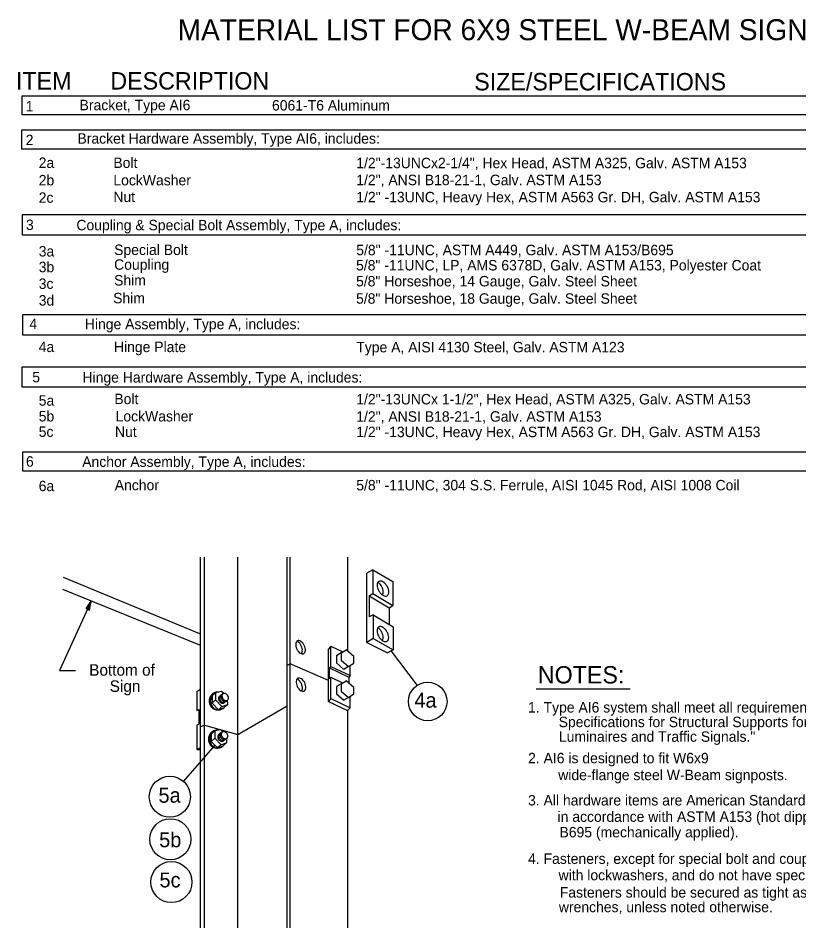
# Model space of a CAD drawing. Extents: x 12.3 to 19.6, y 5.8 to 16.1.
# Drawn here: x 12.33 to 16.82, y 10.9 to 16.09 of the extents above; entities that cross this region are included whole.
import ezdxf

# ---------------------------------------------------------------- set-up
doc = ezdxf.new("R2010")
doc.units = 0
for name, color, linetype in [('DETL-DIMS', 7, 'Continuous'), ('DETL-LINE', 7, 'Continuous'), ('DETL-NOTE', 7, 'Continuous')]:
    doc.layers.add(name, color=color, linetype=linetype)

msp = doc.modelspace()

# ---------------------------------------------------------------- linework, layer by layer
at = {"layer": 'DETL-DIMS'}
for p, q in [((12.7167, 12.6931), (12.7467, 12.7361)), ((12.7467, 12.7361), (12.7217, 12.6911)), ((12.7257, 12.6891), (12.7467, 12.7361)), ((12.7467, 12.7361), (12.7307, 12.6871)), ((12.7357, 12.6851), (12.7467, 12.7361)), ((12.7167, 12.6931), (12.7357, 12.6851))]:
    msp.add_line(p, q, dxfattribs=at)
msp.add_lwpolyline([(12.7467, 12.7361), (12.5633, 12.3374), (12.6551, 12.3374)], dxfattribs=at)
at = {"layer": 'DETL-LINE'}
for p, q in [((13.3751, 8.942), (13.3751, 12.9888)), ((13.3981, 8.9369), (13.3981, 12.9888)), ((13.5899, 8.9603), (13.5899, 12.9888)), ((13.8741, 8.7423), (13.8741, 12.9888)), ((13.8901, 8.7359), (13.8901, 12.9888)), ((14.2196, 12.9888), (14.2196, 12.4502)), ((14.3668, 12.9167), (14.3308, 12.8962)), ((14.3308, 12.4991), (14.3308, 12.8962)), ((14.3668, 12.9167), (14.4816, 12.8481)), ((14.3668, 12.9167), (14.3668, 12.7802)), ((13.3716, 12.5481), (12.5869, 12.8713)), ((14.4816, 12.8481), (14.4816, 12.7115)), ((13.3709, 12.4829), (12.5823, 12.8027)), ((14.3451, 12.7669), (14.3668, 12.7802)), ((14.3668, 12.7802), (14.4816, 12.7115)), ((14.3451, 12.7669), (14.4599, 12.6983)), ((14.3451, 12.7669), (14.3451, 12.6452)), ((14.4599, 12.6983), (14.4816, 12.7115)), ((14.4599, 12.6983), (14.4599, 12.6022)), ((14.3685, 12.6569), (14.3451, 12.6452)), ((14.3685, 12.6569), (14.4833, 12.5882)), ((14.3685, 12.6569), (14.3685, 12.5206)), ((14.4833, 12.5882), (14.4833, 12.457)), ((14.3685, 12.5206), (14.3308, 12.4991)), ((14.3685, 12.5206), (14.4833, 12.457)), ((14.1242, 12.4766), (14.1102, 12.46)), ((14.1242, 12.4766), (14.1934, 12.4443)), ((14.1242, 12.3611), (14.1242, 12.4766)), ((14.3308, 12.4991), (14.4511, 12.4385)), ((14.1102, 12.1591), (14.1102, 12.46)), ((14.1847, 12.4392), (14.157, 12.4223)), ((14.157, 12.4237), (14.157, 12.3805)), ((14.1832, 12.4383), (14.213, 12.456)), ((14.1832, 12.4396), (14.1832, 12.3964)), ((14.2562, 12.418), (14.213, 12.456)), ((14.2562, 12.38), (14.2562, 12.418)), ((14.4833, 12.457), (14.4511, 12.4385)), ((13.8901, 12.3763), (13.8741, 12.3656)), ((14.1102, 12.279), (13.8901, 12.3763)), ((14.1242, 12.3611), (14.1163, 12.3517)), ((14.1242, 12.3611), (14.2363, 12.3079)), ((14.157, 12.3805), (14.2002, 12.3435)), ((14.1832, 12.3964), (14.2264, 12.3595)), ((14.2264, 12.3595), (14.2002, 12.3435)), ((14.2264, 12.3595), (14.2562, 12.38)), ((14.2363, 12.3079), (14.2363, 12.3663)), ((14.1163, 12.3517), (14.2284, 12.2985)), ((14.1163, 12.2887), (14.1163, 12.3517)), ((14.2363, 12.3079), (14.2284, 12.2985)), ((14.1242, 12.2981), (14.1163, 12.2887)), ((14.1242, 12.2981), (14.1922, 12.2659)), ((14.1242, 12.1757), (14.1242, 12.2981)), ((14.1847, 12.2614), (14.157, 12.2446)), ((14.1832, 12.2605), (14.213, 12.2783)), ((14.1832, 12.2619), (14.1832, 12.2187)), ((14.2562, 12.2403), (14.213, 12.2783)), ((14.2284, 12.2985), (14.2284, 12.2648)), ((13.3767, 12.23), (13.353, 12.2151)), ((13.353, 12.2151), (13.353, 12.1071)), ((13.4613, 12.2094), (13.4412, 12.1906)), ((13.495, 12.2164), (13.4613, 12.2094)), ((13.4613, 12.2094), (13.4613, 12.1678)), ((13.5041, 12.2031), (13.4814, 12.1857)), ((13.5092, 12.2053), (13.495, 12.2164)), ((14.157, 12.2459), (14.157, 12.2027)), ((14.157, 12.2027), (14.2002, 12.1658)), ((14.1832, 12.2187), (14.2264, 12.1817)), ((14.2264, 12.1817), (14.2562, 12.2023)), ((14.2562, 12.2023), (14.2562, 12.2403)), ((13.4412, 12.1906), (13.4412, 12.1489)), ((13.4613, 12.1678), (13.4412, 12.1489)), ((13.4613, 12.1678), (13.4976, 12.1301)), ((13.5277, 12.1649), (13.5098, 12.1512)), ((13.5313, 12.1425), (13.5297, 12.166)), ((14.1242, 12.1757), (14.1102, 12.1591)), ((14.1102, 12.1591), (14.2196, 12.1081)), ((14.1242, 12.1757), (14.2363, 12.1234)), ((14.2264, 12.1817), (14.2002, 12.1658)), ((14.2363, 12.1234), (14.2363, 12.1885)), ((13.353, 12.1071), (13.3646, 12.1123)), ((13.3646, 12.1123), (13.3646, 12.0282)), ((13.4412, 12.1489), (13.4775, 12.1113)), ((13.4976, 12.1301), (13.4775, 12.1113)), ((13.4775, 12.1113), (13.5112, 12.1237)), ((13.4976, 12.1301), (13.5313, 12.1425)), ((13.5313, 12.1425), (13.5114, 12.1254)), ((13.5899, 11.969), (13.8741, 12.1331)), ((14.2363, 12.1234), (14.2196, 12.1081)), ((14.2196, 12.1081), (14.2196, 9.0896)), ((13.353, 12.0229), (13.3646, 12.0282)), ((13.353, 12.0229), (13.353, 11.8832)), ((13.3751, 12.0147), (13.3981, 12.0221)), ((13.3981, 12.0221), (13.5899, 11.969)), ((13.4908, 11.9969), (13.4571, 11.9899)), ((13.505, 11.9858), (13.4908, 11.9969)), ((13.4571, 11.9899), (13.437, 11.9711)), ((13.437, 11.9711), (13.437, 11.9294)), ((13.4571, 11.9483), (13.437, 11.9294)), ((13.4571, 11.9899), (13.4571, 11.9483)), ((13.4571, 11.9483), (13.4934, 11.9106)), ((13.5, 11.9836), (13.4773, 11.9662)), ((13.5236, 11.9454), (13.5057, 11.9317)), ((13.5272, 11.923), (13.5256, 11.9465)), ((13.353, 11.8832), (13.3743, 11.8952)), ((13.437, 11.9294), (13.4733, 11.8918)), ((13.4934, 11.9106), (13.4733, 11.8918)), ((13.4733, 11.8918), (13.507, 11.9042)), ((13.4934, 11.9106), (13.5272, 11.923)), ((13.5272, 11.923), (13.5072, 11.9059)), ((13.353, 11.8832), (13.3742, 11.8832))]:
    msp.add_line(p, q, dxfattribs=at)
for centre, radius, start, end in [((14.4255, 12.8279), 0.0347, 155.6571, 180), ((14.4451, 12.8279), 0.0543, 180, 196.5505), ((14.4089, 12.8354), 0.0164, 120, 155.6571), ((14.3652, 12.8008), 0.0543, 43.4495, 55.4689), ((14.4089, 12.8354), 0.0164, 84.3429, 120), ((14.3451, 12.7818), 0.082, 30, 43.4495), ((14.4071, 12.8172), 0.0347, 60, 84.3429), ((14.3973, 12.8002), 0.0543, 43.4495, 60), ((14.3772, 12.7812), 0.082, 30, 43.4495), ((14.4717, 12.8358), 0.082, 196.5505, 210), ((14.4717, 12.8358), 0.082, 210, 223.4495), ((14.4516, 12.8167), 0.0543, 223.4495, 240), ((14.3451, 12.7818), 0.082, 16.5505, 30), ((14.4079, 12.7822), 0.0164, 321.6077, 335.6571), ((14.3913, 12.7897), 0.0347, 335.6571, 360), ((14.3717, 12.7897), 0.0543, 0, 16.5505), ((14.3772, 12.7812), 0.082, 16.5505, 30), ((14.44, 12.7815), 0.0164, 300, 335.6571), ((14.4234, 12.7891), 0.0347, 335.6571, 360), ((14.4037, 12.7891), 0.0543, 360, 16.5505), ((14.4418, 12.7997), 0.0347, 240, 264.3429), ((14.44, 12.7815), 0.0164, 264.3429, 300), ((14.4249, 12.5659), 0.0347, 155.6571, 180), ((14.4445, 12.5659), 0.0543, 180, 196.5505), ((14.4083, 12.5734), 0.0164, 120, 155.6571), ((14.3646, 12.5389), 0.0543, 43.4495, 55.4689), ((14.4083, 12.5734), 0.0164, 84.3429, 120), ((14.3445, 12.5198), 0.082, 30, 43.4495), ((14.4065, 12.5552), 0.0347, 60, 84.3429), ((14.3967, 12.5382), 0.0543, 43.4495, 60), ((14.3766, 12.5192), 0.082, 30, 43.4495), ((14.4711, 12.5738), 0.082, 196.5505, 210), ((14.4711, 12.5738), 0.082, 210, 223.4495), ((14.451, 12.5547), 0.0543, 223.4495, 240), ((14.3445, 12.5198), 0.082, 16.5505, 30), ((14.4073, 12.5202), 0.0164, 321.6077, 335.6571), ((14.3907, 12.5277), 0.0347, 335.6571, 0), ((14.3711, 12.5277), 0.0543, 360, 16.5505), ((14.3766, 12.5192), 0.082, 16.5505, 30), ((14.4228, 12.5271), 0.0347, 335.6571, 0), ((14.4031, 12.5271), 0.0543, 0, 16.5505), ((13.9694, 12.4861), 0.0468, 175.701, 192.2515), ((13.9525, 12.4874), 0.0299, 151.3581, 175.701), ((13.9928, 12.4912), 0.0707, 192.2515, 205.701), ((13.9387, 12.4949), 0.0142, 115.701, 151.3581), ((13.9186, 12.4784), 0.0299, 55.701, 67.6796), ((13.9387, 12.4949), 0.0142, 80.0438, 115.701), ((13.9091, 12.4644), 0.0468, 39.1504, 55.701), ((13.936, 12.4794), 0.0299, 55.701, 80.0438), ((13.8905, 12.4493), 0.0707, 25.701, 39.1504), ((13.9265, 12.4654), 0.0468, 39.1504, 55.701), ((13.8905, 12.4493), 0.0707, 12.2515, 25.701), ((13.9139, 12.4544), 0.0468, 355.701, 12.2515), ((13.9079, 12.4503), 0.0707, 25.701, 39.1504), ((13.9079, 12.4503), 0.0707, 12.2515, 25.701), ((13.9313, 12.4554), 0.0468, 355.701, 12.2515), ((14.4412, 12.5377), 0.0347, 240, 264.3429), ((14.4394, 12.5195), 0.0164, 264.3429, 300), ((14.4394, 12.5195), 0.0164, 300, 335.6571), ((13.9928, 12.4912), 0.0707, 205.701, 219.1504), ((13.9742, 12.4761), 0.0468, 219.1504, 235.701), ((13.9647, 12.4621), 0.0299, 235.701, 260.0438), ((13.9446, 12.4456), 0.0142, 308.1326, 331.3581), ((13.9308, 12.4531), 0.0299, 331.3581, 355.701), ((13.962, 12.4466), 0.0142, 260.0438, 295.701), ((13.962, 12.4466), 0.0142, 295.701, 331.3581), ((13.9482, 12.4541), 0.0299, 331.3581, 355.701), ((13.9721, 12.2711), 0.0468, 175.701, 192.2515), ((13.9552, 12.2724), 0.0299, 151.3581, 175.701), ((13.9955, 12.2762), 0.0707, 192.2515, 205.701), ((13.9414, 12.2799), 0.0142, 115.701, 151.3581), ((13.9194, 12.26), 0.0299, 55.701, 69.5858), ((13.9414, 12.2799), 0.0142, 80.0438, 115.701), ((13.9098, 12.246), 0.0468, 39.1504, 55.701), ((13.9387, 12.2644), 0.0299, 55.701, 80.0438), ((13.8913, 12.2309), 0.0707, 25.701, 39.1504), ((13.8913, 12.2309), 0.0707, 12.2515, 25.701), ((13.9292, 12.2504), 0.0468, 39.1504, 55.701), ((13.9106, 12.2353), 0.0707, 25.701, 39.1504), ((13.9106, 12.2353), 0.0707, 12.2515, 25.701), ((13.4732, 12.1668), 0.0468, 114.7547, 138.0665), ((13.4809, 12.1668), 0.0468, 114.7547, 138.0665), ((13.471, 12.1716), 0.0416, 90, 114.7547), ((13.4787, 12.1716), 0.0416, 90, 114.7547), ((13.471, 12.1716), 0.0416, 84.6565, 90), ((13.4787, 12.1716), 0.0416, 88.6972, 90), ((13.5116, 12.1928), 0.0127, 125.0637, 154.1238), ((13.5116, 12.1928), 0.0127, 96.0036, 125.0637), ((13.5121, 12.1874), 0.0181, 71.7651, 96.0036), ((13.5105, 12.1825), 0.0233, 52.2224, 71.7651), ((13.9955, 12.2762), 0.0707, 205.701, 219.1504), ((13.9769, 12.2611), 0.0468, 219.1504, 235.701), ((13.9674, 12.2471), 0.0299, 235.701, 260.0438), ((13.9453, 12.2271), 0.0142, 325.3044, 331.3581), ((13.9315, 12.2347), 0.0299, 331.3581, 355.701), ((13.9146, 12.2359), 0.0468, 355.701, 12.2515), ((13.9647, 12.2316), 0.0142, 260.0438, 295.701), ((13.9647, 12.2316), 0.0142, 295.701, 331.3581), ((13.9509, 12.2391), 0.0299, 331.3581, 355.701), ((13.934, 12.2404), 0.0468, 355.701, 12.2515), ((13.4819, 12.1618), 0.0571, 159.5903, 180), ((13.4819, 12.1618), 0.0571, 180, 200.4097), ((13.4766, 12.1638), 0.0514, 138.0665, 159.5903), ((13.4897, 12.1618), 0.0571, 159.5903, 180), ((13.4897, 12.1618), 0.0571, 180, 200.4097), ((13.4843, 12.1638), 0.0514, 138.0665, 159.5903), ((13.4963, 12.1755), 0.0181, 154.1238, 178.3623), ((13.5015, 12.1754), 0.0233, 178.3623, 197.905), ((13.5081, 12.1775), 0.0302, 197.905, 215.0637), ((13.4915, 12.1779), 0.0127, 142.3349, 154.1238), ((13.5081, 12.1775), 0.0302, 215.0637, 232.2224), ((13.5023, 12.1798), 0.0181, 154.1238, 178.3623), ((13.5075, 12.1796), 0.0233, 178.3623, 197.905), ((13.514, 12.1817), 0.0302, 197.905, 215.0637), ((13.4975, 12.1821), 0.0127, 142.3349, 154.1238), ((13.514, 12.1817), 0.0302, 215.0637, 232.2224), ((13.5038, 12.1721), 0.0233, 232.2224, 251.7651), ((13.5101, 12.1858), 0.0181, 154.1238, 178.3623), ((13.5153, 12.1856), 0.0233, 178.3623, 197.905), ((13.5218, 12.1877), 0.0302, 197.905, 215.0637), ((13.5052, 12.1881), 0.0127, 142.3349, 154.1238), ((13.5098, 12.1763), 0.0233, 232.2224, 251.7651), ((13.5022, 12.1671), 0.0181, 251.7651, 276.0036), ((13.5218, 12.1877), 0.0302, 215.0637, 232.2224), ((13.5165, 12.1904), 0.0181, 154.1238, 178.3623), ((13.5216, 12.1903), 0.0233, 178.3623, 197.905), ((13.5282, 12.1924), 0.0302, 197.905, 215.0637), ((13.5082, 12.1714), 0.0181, 251.7651, 276.0036), ((13.5176, 12.1823), 0.0233, 232.2224, 251.7651), ((13.5282, 12.1924), 0.0302, 215.0637, 232.2224), ((13.5028, 12.1617), 0.0127, 276.0036, 305.0637), ((13.524, 12.187), 0.0233, 232.2224, 251.7651), ((13.5088, 12.166), 0.0127, 276.0036, 305.0637), ((13.5028, 12.1617), 0.0127, 305.0637, 311.2814), ((13.516, 12.1774), 0.0181, 251.7651, 276.0036), ((13.5223, 12.1821), 0.0181, 251.7651, 276.0036), ((13.5166, 12.172), 0.0127, 276.0036, 305.0637), ((13.5229, 12.1767), 0.0127, 276.0036, 305.0637), ((13.5063, 12.1771), 0.0302, 35.0637, 52.2224), ((13.5229, 12.1767), 0.0127, 305.0637, 334.1238), ((13.5063, 12.1771), 0.0302, 17.905, 35.0637), ((13.518, 12.179), 0.0181, 334.1238, 358.3623), ((13.5128, 12.1792), 0.0233, 358.3623, 17.905), ((13.4766, 12.1598), 0.0514, 200.4097, 221.9335), ((13.4843, 12.1598), 0.0514, 200.4097, 221.9335), ((13.4732, 12.1567), 0.0468, 221.9335, 245.2453), ((13.4809, 12.1567), 0.0468, 221.9335, 245.2453), ((13.471, 12.152), 0.0416, 245.2453, 270), ((13.4787, 12.152), 0.0416, 245.2453, 270), ((13.471, 12.152), 0.0416, 270, 275.3435), ((13.4787, 12.152), 0.0416, 270, 294.7547), ((13.4765, 12.1567), 0.0468, 294.7547, 313.5206), ((13.4668, 11.9521), 0.0416, 90, 114.7547), ((13.4746, 11.9521), 0.0416, 90, 114.7547), ((13.4668, 11.9521), 0.0416, 84.6565, 90), ((13.4746, 11.9521), 0.0416, 88.6972, 90), ((13.4778, 11.9423), 0.0571, 159.5903, 180), ((13.4778, 11.9423), 0.0571, 180, 200.4097), ((13.4724, 11.9443), 0.0514, 138.0665, 159.5903), ((13.4855, 11.9423), 0.0571, 159.5903, 180), ((13.4855, 11.9423), 0.0571, 180, 200.4097), ((13.4802, 11.9443), 0.0514, 138.0665, 159.5903), ((13.469, 11.9473), 0.0468, 114.7547, 138.0665), ((13.4768, 11.9473), 0.0468, 114.7547, 138.0665), ((13.4922, 11.956), 0.0181, 154.1238, 178.3623), ((13.4974, 11.9559), 0.0233, 178.3623, 197.905), ((13.5039, 11.958), 0.0302, 197.905, 215.0637), ((13.4873, 11.9584), 0.0127, 142.3349, 154.1238), ((13.4982, 11.9603), 0.0181, 154.1238, 178.3623), ((13.5034, 11.9601), 0.0233, 178.3623, 197.905), ((13.5099, 11.9622), 0.0302, 197.905, 215.0637), ((13.4933, 11.9626), 0.0127, 142.3349, 154.1238), ((13.5099, 11.9622), 0.0302, 215.0637, 232.2224), ((13.5059, 11.9663), 0.0181, 154.1238, 178.3623), ((13.5111, 11.9661), 0.0233, 178.3623, 197.905), ((13.5177, 11.9682), 0.0302, 197.905, 215.0637), ((13.5011, 11.9686), 0.0127, 142.3349, 154.1238), ((13.5177, 11.9682), 0.0302, 215.0637, 232.2224), ((13.5123, 11.9709), 0.0181, 154.1238, 178.3623), ((13.5175, 11.9708), 0.0233, 178.3623, 197.905), ((13.524, 11.9729), 0.0302, 197.905, 215.0637), ((13.5074, 11.9733), 0.0127, 125.0637, 154.1238), ((13.5135, 11.9628), 0.0233, 232.2224, 251.7651), ((13.524, 11.9729), 0.0302, 215.0637, 232.2224), ((13.5074, 11.9733), 0.0127, 96.0036, 125.0637), ((13.5198, 11.9675), 0.0233, 232.2224, 251.7651), ((13.508, 11.9679), 0.0181, 71.7651, 96.0036), ((13.5182, 11.9626), 0.0181, 251.7651, 276.0036), ((13.5064, 11.963), 0.0233, 52.2224, 71.7651), ((13.5124, 11.9525), 0.0127, 276.0036, 305.0637), ((13.5188, 11.9572), 0.0127, 276.0036, 305.0637), ((13.5022, 11.9576), 0.0302, 35.0637, 52.2224), ((13.5188, 11.9572), 0.0127, 305.0637, 334.1238), ((13.5022, 11.9576), 0.0302, 17.905, 35.0637), ((13.5139, 11.9595), 0.0181, 334.1238, 358.3623), ((13.5087, 11.9597), 0.0233, 358.3623, 17.905), ((13.4724, 11.9403), 0.0514, 200.4097, 221.9335), ((13.4802, 11.9403), 0.0514, 200.4097, 221.9335), ((13.469, 11.9372), 0.0468, 221.9335, 245.2453), ((13.4768, 11.9372), 0.0468, 221.9335, 245.2453), ((13.4668, 11.9325), 0.0416, 245.2453, 270), ((13.4746, 11.9325), 0.0416, 245.2453, 270), ((13.4668, 11.9325), 0.0416, 270, 275.3435), ((13.4746, 11.9325), 0.0416, 270, 294.7547), ((13.5039, 11.958), 0.0302, 215.0637, 232.2224), ((13.4997, 11.9526), 0.0233, 232.2224, 251.7651), ((13.5057, 11.9568), 0.0233, 232.2224, 251.7651), ((13.4724, 11.9372), 0.0468, 294.7547, 313.5206), ((13.4981, 11.9476), 0.0181, 251.7651, 276.0036), ((13.5041, 11.9519), 0.0181, 251.7651, 276.0036), ((13.4986, 11.9422), 0.0127, 276.0036, 305.0637), ((13.4986, 11.9422), 0.0127, 305.0637, 311.2814), ((13.5046, 11.9465), 0.0127, 276.0036, 305.0637), ((13.5118, 11.9579), 0.0181, 251.7651, 276.0036)]:
    msp.add_arc(centre, radius, start, end, dxfattribs=at)
at = {"layer": 'DETL-NOTE'}
for p, q in [((14.4711, 12.4488), (14.6203, 12.251)), ((15.3063, 12.2315), (15.8462, 12.2315)), ((13.4574, 11.9083), (13.2762, 11.6999))]:
    msp.add_line(p, q, dxfattribs=at)
for points in [[(12.3489, 15.6418), (18.3923, 15.6418), (18.3923, 15.5318), (12.3489, 15.5318)], [(12.3469, 15.4458), (18.3923, 15.4458), (18.3923, 15.3358), (12.3469, 15.3358)], [(12.3489, 14.957), (12.3489, 14.8422), (18.3923, 14.8422), (18.3923, 14.957)], [(12.3506, 14.3821), (12.3506, 14.2674), (18.3986, 14.2674), (18.3986, 14.3821)], [(12.3469, 14.0822), (12.3469, 13.9675), (18.3923, 13.9675), (18.3923, 14.0822)], [(12.3511, 13.5929), (12.3511, 13.4862), (18.3986, 13.4862), (18.3986, 13.5929)]]:
    msp.add_lwpolyline(points, close=True, dxfattribs=at)
for centre, radius in [((14.682, 12.159), 0.1108), ((13.1984, 11.6111), 0.1181), ((13.2017, 11.3669), 0.1181), ((13.2075, 11.1204), 0.1181)]:
    msp.add_circle(centre, radius, dxfattribs=at)

# ---------------------------------------------------------------- texts
at = {"layer": 'DETL-DIMS'}
for s, p in [('Bottom of', (12.7346, 12.3074)), ('Sign', (12.8525, 12.2143))]:
    msp.add_text(s, height=0.066, dxfattribs=at).set_placement(p)
at = {"layer": 'DETL-NOTE'}
for s, height, p in [('MATERIAL LIST FOR 6X9 STEEL W-BEAM SIGN POSTS (AI6)', 0.121002, (13.2432, 15.9617)), ('ITEM', 0.1, (12.3129, 15.6781)), ('DESCRIPTION', 0.1, (12.8561, 15.6781)), ('SIZE/SPECIFICATIONS', 0.1, (14.9494, 15.6731)), ('1', 0.06, (12.3695, 15.5528)), ('Bracket, Type AI6', 0.06, (12.6792, 15.5589)), ('6061-T6 Aluminum', 0.06, (13.7862, 15.5574)), ('Bracket Hardware Assembly, Type AI6, includes:', 0.06, (12.6671, 15.3668)), ('2', 0.06, (12.3695, 15.3583)), ('2a ', 0.06, (12.4442, 15.2271)), ('Bolt', 0.06, (12.8736, 15.2271)), ('1/2"-13UNCx2-1/4", Hex Head, ASTM A325, Galv. ASTM A153', 0.06, (14.2709, 15.2256)), ('2b ', 0.06, (12.4442, 15.1269)), ('LockWasher', 0.06, (12.8736, 15.1269)), ('1/2", ANSI B18-21-1, Galv. ASTM A153', 0.06, (14.2709, 15.1281)), ('2c ', 0.06, (12.4442, 15.0267)), ('Nut', 0.06, (12.8736, 15.0311)), ('1/2" -13UNC, Heavy Hex, ASTM A563 Gr. DH, Galv. ASTM A153', 0.06, (14.2709, 15.0297)), ('3', 0.06, (12.3709, 14.8702)), ('Coupling & Special Bolt Assembly, Type A, includes:', 0.06, (12.661, 14.8687)), ('3a', 0.06, (12.4442, 14.718)), ('Special Bolt', 0.06, (12.878, 14.7266)), ('5/8" -11UNC, ASTM A449, Galv. ASTM A153/B695', 0.06, (14.2709, 14.7252)), ('Coupling', 0.06, (12.878, 14.6418)), ('5/8" -11UNC, LP, AMS 6378D, Galv. ASTM A153, Polyester Coat', 0.06, (14.2697, 14.6378)), ('3b', 0.06, (12.4442, 14.6275)), ('3c', 0.06, (12.4442, 14.5316)), ('Shim', 0.06, (12.8777, 14.5512)), ('5/8" Horseshoe, 14 Gauge, Galv. Steel Sheet', 0.06, (14.2697, 14.546)), ('3d', 0.06, (12.4442, 14.4358)), ('Shim', 0.06, (12.8724, 14.4489)), ('5/8" Horseshoe, 18 Gauge, Galv. Steel Sheet', 0.06, (14.2697, 14.4463)), ('4      ', 0.06, (12.3909, 14.3011)), ('Hinge Assembly, Type A, includes:', 0.06, (12.7095, 14.2996)), ('4a', 0.06, (12.4442, 14.1685)), ('Hinge Plate', 0.06, (12.877, 14.1681)), ('Type A, AISI 4130 Steel, Galv. ASTM A123 ', 0.06, (14.2709, 14.1667)), ('5                    ', 0.06, (12.4071, 13.9946)), ('Hinge Hardware Assembly, Type A, includes:', 0.06, (12.6959, 13.9932)), ('5a', 0.06, (12.4442, 13.8599)), ('Bolt', 0.06, (12.8793, 13.8688)), ('1/2"-13UNCx 1-1/2", Hex Head, ASTM A325, Galv. ASTM A153', 0.06, (14.2709, 13.8674)), ('5b ', 0.06, (12.4442, 13.7694)), ('LockWasher   ', 0.06, (12.8864, 13.7694)), ('1/2", ANSI B18-21-1, Galv. ASTM A153 ', 0.06, (14.2709, 13.768)), ('5c ', 0.06, (12.4442, 13.6806)), ('Nut ', 0.06, (12.8828, 13.6806)), ('1/2" -13UNC, Heavy Hex, ASTM A563 Gr. DH, Galv. ASTM A153', 0.06, (14.2709, 13.6792)), ('6', 0.06, (12.3709, 13.5094)), ('Anchor Assembly, Type A, includes:', 0.06, (12.6944, 13.508)), ('6a', 0.06, (12.4442, 13.3685)), ('Anchor', 0.06, (12.8816, 13.3736)), ('5/8" -11UNC, 304 S.S. Ferrule, AISI 1045 Rod, AISI 1008 Coil', 0.06, (14.2709, 13.373)), ('NOTES:', 0.1, (15.3154, 12.2625)), ('4a', 0.0858, (14.6053, 12.1234)), ('1. Type AI6 system shall meet all requirements of "AASHTO Standard', 0.06, (15.2591, 12.0954)), ('Specifications for Structural Supports for Highway Signs,', 0.06, (15.4352, 12.0114)), ('Luminaires and Traffic Signals."', 0.06, (15.4366, 11.9274)), ('2. AI6 is designed to fit W6x9', 0.06, (15.2591, 11.8036)), ('wide-flange steel W-Beam signposts.', 0.06, (15.4325, 11.7066)), ('5a', 0.0858, (13.1331, 11.5769)), ('3. All hardware items are American Standard sizes, galvanized', 0.06, (15.2591, 11.5611)), ('in accordance with ASTM A153 (hot dipped) or ASTM', 0.06, (15.4287, 11.4668)), ('B695 (mechanically applied).              ', 0.06, (15.4399, 11.3776)), ('5b', 0.0858, (13.1369, 11.3208)), ('4. Fasteners, except for special bolt and coupling, are installed', 0.06, (15.2591, 11.2251)), ('5c', 0.0858, (13.1388, 11.0898)), ('with lockwashers, and do not have specific torque requirements.', 0.06, (15.4348, 11.1308)), ('Fasteners should be secured as tight as possible with conventional', 0.06, (15.4415, 11.0313)), ('wrenches, unless noted otherwise.', 0.06, (15.4362, 10.9473))]:
    msp.add_text(s, height=height, dxfattribs=at).set_placement(p)

doc.saveas('drawing.dxf')
